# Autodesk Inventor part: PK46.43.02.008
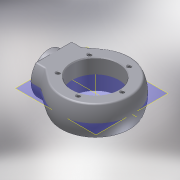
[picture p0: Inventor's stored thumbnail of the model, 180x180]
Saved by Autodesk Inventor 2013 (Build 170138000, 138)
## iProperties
Shininess: 20.0
Length Units: 11269
Angle Units: 11279
Time Units: 11290
Mass Units: 11283
Length Display Precision: 3
Angle Display Precision: 2
Created: 2001-08
Part Number: PK46.43.02.008
Material: Steel, Mild
Document SubType Name: Modeling
Designer: SOleg
Density: 7.86 g/cm^3
Density: 0.0
Volumn: 0.0
Area: 0.0
PropertySet Name: Model Information
Control State: 0
Master: False
Checked Out: True
Checked Out Date: 2008-10-09
Last Check In Date: 2008-10-09
Author: SOleg
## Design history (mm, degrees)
node "WorkPlane3"
node "WorkPlane1"
node "WorkPlane4"
sketch "Sketch3"
  geometry: L1 (-121.126, -62.5)-(-121.126, 0); L2 (-81.126, -62.5)-(-121.126, -62.5); L3 (-45.862, -83.69)-(-75.862, -64.069); L4 (-121.126, 0)-(108.874, 0); L5 (-121.126, 0)-(108.874, 0); A1 r 9.617 centre (-81.126, -72.117) between (-75.862, -64.069) and (-81.126, -62.5); A2 r 100 centre (8.874, 0) between (-45.862, -83.69) and (108.874, 0)
  constraints: 10 end point, 4 point on circle, 3 tangent, 2 centre point, 2 horizontal, 1 vertical, 1 other
  dimensions: "d2" = 130 horizontal distance of A2.centre L1.start; "d4" = 0 vertical distance of A2.centre L4.end; "d6" = 100 radius of A2; "d8" = 40 distance of L2.start L1.start; "d10" = 62.5 distance of L1.start L1.end; "d12" = 30 horizontal distance of L3.start L3.end
revolve "RevolutionAngle1" sketch "Sketch3" stored, may be unused: angle "d13" = 360 deg
sketch "Sketch4"
  geometry: L1 (-108.874, 140)-(-108.874, 40); L2 (141.126, 140)-(-108.874, 140); L3 (141.126, 55)-(141.126, 140); L4 (-108.874, 40)-(126.126, 40); L5 (-108.874, -140)-(-108.874, -40); L6 (141.126, -140)-(-108.874, -140); L7 (141.126, -55)-(141.126, -140); L8 (-108.874, -40)-(126.126, -40); C1 r 62.5 at (121.126, 0); A1 r 15 centre (126.126, 55) between (126.126, 40) and (141.126, 55); A2 r 15 centre (126.126, -55) between (141.126, -55) and (126.126, -40)
  constraints: 16 end point, 4 horizontal, 4 point on circle, 4 tangent, 3 centre point, 3 vertical, 1 collinear
  dimensions: "d16" = 80 distance of L5.end L1.end; "d18" = 15 radius of A1; "d20" = 100 distance of L1.start L1.end; "d22" = 100 distance of L5.start L5.end; "d24" = 250 horizontal distance of L5.end L2.start; "d26" = 250 distance of L6.start L5.start; "d28" = 20 horizontal distance of L3.start C1.centre
extrude "ExtrusionMidplane1" cut sketch "Sketch4" stored distance "d29" = 200; taper "d30" = 0 deg
sketch "Sketch5"
  geometry: C1 r 26 at (0, 0)
  constraints: 1 centre point
  dimensions: "d32" = 52 diameter of C1
extrude "ExtrusionMidplane2" cut sketch "Sketch5" stored distance "d33" = 53; taper "d34" = 0 deg
revolve "RevolutionAngle3" stored, may be unused: angle "d40" = 360 deg
revolve "RevolutionAngle4" stored, may be unused: angle "d49" = 360 deg
sketch "Sketch8"
  geometry: C1 r 2 at (72.126, 0); C2 r 30 at (121.126, 0)
  constraints: 2 centre point
  dimensions: "d51" = 49 distance of C1.centre C2.centre; "d53" = 4 diameter of C1
extrude "ExtrusionMidplane3" cut sketch "Sketch8" stored distance "d54" = 150; taper "d55" = 0 deg
sketch "Эскиз12"
  geometry: L1 (130, -30)-(130, 30) reference; L2 (115, -19.365)-(115, -19.365) reference; L3 (115, 19.365)-(115, 19.365) reference; L4 (126.36, 40)-(126.36, -40) reference; A1 r 88.318 centre (0, 0) between (51.999, 71.387) and (51.999, -71.387) reference; 3 further points
  dimensions: "d85" = 130 distance from line of L1 point (0, 0); "d86" = 0 distance of A1.centre point (0, 0)
hole "Отверстие2" sketch "Эскиз12" diameter "d87" = 125; stored, may be unused: countersink angle "d91" = 82 deg, drill point angle "d93" = 118 deg; dims "d88" = 6, "d89" = 129, "d90" = 2, "d92" = 40
node "РабПлоскость4"
mirror "ЗеркОтобр1"
node "РабОсь4"
sketch "Эскиз13"
  geometry: L1 (-176, 0)-(146, 0) reference; L2 (-130, 30)-(-130, -30) reference; C1 r 64.5 at (0, 0) reference; 1 further point
  dimensions: "d100" = 0 distance from line of point (72.5, 0) L1; "d101" = 72.5 distance of C1.centre point (72.5, 0)
hole "Отверстие3" sketch "Эскиз13" diameter "d102" = 10; stored, may be unused: countersink angle "d106" = 82 deg, drill point angle "d108" = 118 deg; dims "d103" = 6, "d104" = 13.2, "d105" = 2, "d107" = 16
feature "Резьба2" dims "d109" = 10, "d110" = 0
node "РабОсь5"
pattern_circular "Круговой массив2" dims angle "d113" = 360 deg
feature "Резьба3" dims "d114" = 10, "d115" = 0
feature "Резьба4" dims "d116" = 10, "d117" = 0
feature "Резьба5" dims "d118" = 10, "d119" = 0
feature "Резьба6" dims "d120" = 10, "d121" = 0
mirror "ЗеркОтобр2"
feature "Резьба7" dims "d122" = 10, "d123" = 0
feature "Резьба8" dims "d124" = 10, "d125" = 0
feature "Резьба9" dims "d126" = 10, "d127" = 0
feature "Резьба10" dims "d128" = 10, "d129" = 0
feature "Резьба11" dims "d130" = 10, "d131" = 0
feature "Резьба12" dims "d132" = 10, "d133" = 0
sketch "Эскиз14"
  geometry: C1 r 26 at (35, -19.365); A1 r 40 centre (35, -19.365) between (70, 0) and (0, 0) reference
  constraints: 1 centre point, 1 coincident
  dimensions: "d134" = 52 diameter of C1
extrude "Выдавливание4" cut sketch "Эскиз14" distance "d135" = 37; taper "d136" = 0 deg
body "Solid1"
fillet "Fillet1" dims "d69" = 5
fillet "Fillet2" dims "d70" = 5
node "WorkPlane2"
sketch "Sketch6"
  geometry: L1 (89.626, 0)-(94.626, 0); L2 (94.626, 25)-(89.626, 0); L3 (94.626, 0)-(94.626, 25); L4 (-192.376, 0)-(192.376, 0); L5 (94.626, 0)-(94.626, 1); L6 (-192.376, 0)-(192.376, 0)
  constraints: 12 end point, 2 collinear, 1 horizontal
  dimensions: "d37" = 25 distance of L1.end L2.start; "d39" = 5 distance of L1.start L1.end
sketch "Sketch7"
  geometry: L1 (-117.487, 40)-(-106.126, 40); L2 (-121.126, 30)-(-117.487, 40); L3 (-121.126, 62.5)-(-121.126, 30); L4 (-106.126, 62.5)-(-121.126, 62.5); L5 (-106.126, 40)-(-106.126, 62.5); L6 (-163.686, 0)-(151.433, 0)
  constraints: 12 end point, 2 horizontal, 2 vertical
  dimensions: "d42" = 15 distance of L4.start L3.start; "d44" = 20 deg angle of L2 L3; "d46" = 32.5 distance of L3.start L2.start; "d48" = 22.5 distance of L1.end L4.start
node "Спроецированная петля1"
other parameters: "d3" = 0 (derived), "d9" = 62.5 (derived), "d14" = 0, "d17" = 15 (derived), "d31" = 52 (derived), "d35" = 0, "d36" = 25 (derived), "d38" = 5 (derived), "d41" = 15 (derived), "d43" = 20 deg (derived), "d45" = 32.5 (derived), "d47" = 22.5 (derived), "d50" = 49 (derived), "d52" = 4 (derived), "d56" = 5 (derived), "d58" = 5 (derived), "d60" = 5 (derived), "d62" = 5 (derived), "d64" = 57.5 (derived)
